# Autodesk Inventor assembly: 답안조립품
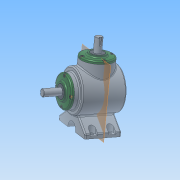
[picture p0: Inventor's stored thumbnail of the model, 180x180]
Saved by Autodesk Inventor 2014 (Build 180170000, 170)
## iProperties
Created: 2017-04
Part Number: 답안조립품
Document SubType Name: Assembly
Designer: NET
Author: NET
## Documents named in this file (14)
- C:\Users\NET\Desktop\470407V1009\답안조립품.iam
- C:\Users\NET\Desktop\470407V1009\본체.ipt
- C:\Users\NET\Desktop\470407V1009\커버.ipt
- C:\Users\NET\Desktop\470407V1009\볼트 M4.ipt
- C:\Users\NET\Desktop\470407V1009\오일실 17 32 8.ipt
- C:\Users\NET\Desktop\470407V1009\베어링 6203.ipt
- C:\Users\NET\Desktop\470407V1009\메인 축.ipt
- 메인 축.ipt
- C:\Users\NET\Desktop\470407V1009\키 5x5.ipt
- C:\Users\NET\Desktop\470407V1009\메인 베벨기어.ipt
- C:\Users\NET\Desktop\470407V1009\서브 축.ipt
- 서브 축.ipt
- C:\Users\NET\Desktop\470407V1009\키 4x4.ipt
- C:\Users\NET\Desktop\470407V1009\서브 베벨기어.ipt
